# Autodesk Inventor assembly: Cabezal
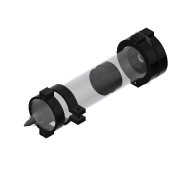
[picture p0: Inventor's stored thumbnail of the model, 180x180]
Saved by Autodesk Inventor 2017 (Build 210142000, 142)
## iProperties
Created: 2018-11
Part Number: Cabezal
Document SubType Name: Assembly
Designer: JK
Author: JK
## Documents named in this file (9)
- C:\Users\JK\Documents\Inventor\BioExtruder\Cabezal.iam
- C:\Users\JK\Documents\Inventor\BioExtruder\Portajeringa60cc.ipt
- C:\Users\JK\Documents\Inventor\BioExtruder\Syringe_60ml_Exterior.ipt
- C:\Users\JK\Documents\Inventor\BioExtruder\PrensaB.ipt
- C:\Users\JK\Documents\Inventor\BioExtruder\PrensaA.ipt
- C:\Users\JK\Documents\Inventor\BioExtruder\Syringe_60ml_rubber.ipt
- C:\Users\JK\Documents\Inventor\BioExtruder\tapacabezal.iam
- C:\Users\JK\Documents\Inventor\BioExtruder\embolocabezal.ipt
- C:\Users\JK\Documents\Inventor\BioExtruder\Tip1mm.ipt
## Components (8 placed, 8 different names)
1. Portajeringa60cc:1 — Mate:1, Angle:1, Mate:2, Angle:2
2. Syringe_60ml_Exterior:1 — Mate:1, Angle:1, Mate:2, Mate:3, Mate:4, Mate:5, Mate:7, Mate:11, Mate:12, Flush:3
3. PrensaB:1 — Mate:3, Angle:2, Mate:4, Mate:6
4. PrensaA:1 — Mate:5, Mate:6, Mate:7, Mate:8, Angle:3, Flush:1, Flush:2
5. tapacabezal:1 [sub-assembly] — Mate:8, Angle:3, Flush:1
6. Syringe_60ml_rubber:1 — Mate:9, Mate:10
7. embolocabezal:1 — Mate:9, Mate:10, Mate:11, Flush:2
8. Tip1mm:1 — Mate:12, Flush:3
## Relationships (18: Mate 12, Angle 3, Flush 3)
- Mate:1: Portajeringa60cc:1 ↔ Syringe_60ml_Exterior:1
- Angle:1: Portajeringa60cc:1 ↔ Syringe_60ml_Exterior:1
- Mate:2: Portajeringa60cc:1 ↔ Syringe_60ml_Exterior:1
- Mate:3: Syringe_60ml_Exterior:1 ↔ PrensaB:1
- Angle:2: Portajeringa60cc:1 ↔ PrensaB:1
- Mate:4: Syringe_60ml_Exterior:1 ↔ PrensaB:1
- Mate:5: Syringe_60ml_Exterior:1 ↔ PrensaA:1
- Mate:6: PrensaB:1 ↔ PrensaA:1
- Mate:7: Syringe_60ml_Exterior:1 ↔ PrensaA:1
- Mate:8: PrensaA:1 ↔ tapacabezal:1
- Angle:3: PrensaA:1 ↔ tapacabezal:1
- Flush:1: PrensaA:1 ↔ tapacabezal:1
- Mate:9: Syringe_60ml_rubber:1 ↔ embolocabezal:1
- Mate:10: Syringe_60ml_rubber:1 ↔ embolocabezal:1
- Mate:11: Syringe_60ml_Exterior:1 ↔ embolocabezal:1
- Flush:2: PrensaA:1 ↔ embolocabezal:1
- Mate:12: Syringe_60ml_Exterior:1 ↔ Tip1mm:1
- Flush:3: Syringe_60ml_Exterior:1 ↔ Tip1mm:1
